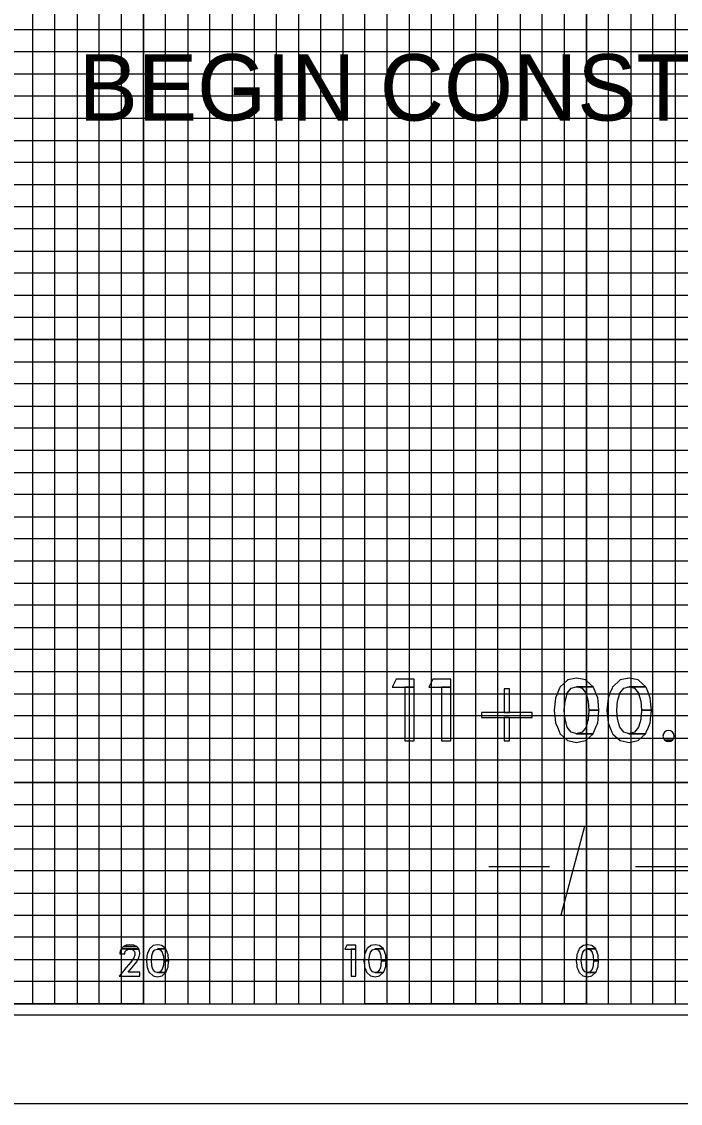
# Model space of a CAD drawing. Extents: x -13 to 323, y -5 to 1431.
# Drawn here: x 134.5 to 164.24, y -4.5 to 44.36 of the extents above; entities that cross this region are included whole.
import ezdxf

# ---------------------------------------------------------------- set-up
doc = ezdxf.new("R2010")
doc.units = 0
for name, color, linetype in [('Prop XS Alignment Label', 7, 'Continuous'), ('Prop XS Offset Labels', 7, 'Continuous'), ('Prop XS Station Labels', 7, 'Continuous'), ('Scratch_Level_3', 7, 'Continuous'), ('Sheet Cross Section CELL', 7, 'Continuous'), ('Sheet Cross Section Grid Major CELL', 7, 'Continuous'), ('Sheet Cross Section Grid Middle CELL', 7, 'Continuous'), ('Sheet Cross Section Grid Minor 1 CELL', 7, 'Continuous'), ('Sheet Cross Section Grid Minor 2 CELL', 7, 'Continuous'), ('Sheet Cutting Line CELL', 7, 'Continuous'), ('Sheet DOT Grid CELL', 7, 'Continuous'), ('Sheet Plot Border Inside CELL', 7, 'Continuous'), ('Sheet Plot Border Outside CELL', 7, 'Continuous')]:
    doc.layers.add(name, color=color, linetype=linetype)

msp = doc.modelspace()

# ---------------------------------------------------------------- linework, layer by layer
at = {"layer": 'Prop XS Alignment Label'}
for p, q in [((155.599, 6.203), (158.324, 6.203)), ((162.211, 6.203), (164.937, 6.203))]:
    msp.add_line(p, q, dxfattribs=at)
msp.add_lwpolyline([(159.913, 8), (158.842, 4), (161.172, 4)], dxfattribs=at)
at = {"layer": 'Prop XS Offset Labels'}
for points in [[(139.051, 1.432), (138.899, 1.25), (139.839, 1.25), (139.839, 1.432), (139.305, 1.432), (139.485, 1.638), (139.681, 1.879), (139.683, 1.881), (139.795, 2.069), (139.794, 2.069), (139.798, 2.074), (139.821, 2.193), (139.833, 2.254), (139.838, 2.279), (139.836, 2.29), (139.835, 2.293), (139.822, 2.354), (139.821, 2.36), (139.819, 2.37), (139.808, 2.421), (139.808, 2.421), (139.805, 2.435), (139.8, 2.461), (139.797, 2.464), (139.794, 2.468), (139.425, 2.468), (139.437, 2.464), (139.445, 2.461), (139.519, 2.435), (139.532, 2.421), (139.583, 2.37), (139.586, 2.36), (139.588, 2.354), (139.609, 2.293), (139.609, 2.29), (139.608, 2.279), (139.608, 2.254), (139.607, 2.193), (139.56, 2.074), (139.558, 2.069), (139.425, 1.881), (139.424, 1.879), (139.223, 1.638)], [(138.935, 2.279), (138.933, 2.254), (139.153, 2.254), (139.155, 2.279), (139.156, 2.29), (139.157, 2.293), (139.179, 2.354), (139.184, 2.36), (139.192, 2.37), (139.232, 2.421), (139.259, 2.435), (139.311, 2.461), (139.317, 2.464), (139.425, 2.468), (139.794, 2.468), (139.784, 2.479), (138.996, 2.479), (138.991, 2.468), (138.989, 2.464), (138.988, 2.461), (138.976, 2.435), (138.97, 2.421), (138.948, 2.37), (138.943, 2.36), (138.942, 2.354), (138.937, 2.293), (138.937, 2.29)], [(139.094, 2.583), (138.996, 2.479), (139.784, 2.479), (139.694, 2.583)], [(139.098, 2.585), (139.094, 2.583), (139.694, 2.583), (139.692, 2.585), (139.56, 2.645), (139.544, 2.652), (139.38, 2.668), (139.38, 2.668), (139.271, 2.652), (139.223, 2.645)], [(140.438, 1.255), (140.637, 1.214), (140.832, 1.255), (140.843, 1.257), (141.008, 1.409), (140.634, 1.409), (140.624, 1.411), (140.619, 1.413), (140.515, 1.442), (140.428, 1.555), (140.427, 1.556), (140.427, 1.556), (140.4, 1.657), (140.399, 1.659), (140.379, 1.732), (140.378, 1.736), (140.36, 1.939), (140.36, 1.941), (140.36, 1.943), (140.378, 2.145), (140.399, 2.222), (140.399, 2.224), (140.426, 2.322), (140.427, 2.325), (140.515, 2.44), (140.627, 2.469), (140.631, 2.47), (140.642, 2.473), (141.012, 2.473), (140.848, 2.622), (140.84, 2.624), (140.639, 2.668), (140.639, 2.668), (140.431, 2.624), (140.429, 2.622), (140.268, 2.473), (140.265, 2.47), (140.264, 2.469), (140.252, 2.44), (140.205, 2.325), (140.203, 2.322), (140.163, 2.224), (140.162, 2.222), (140.155, 2.145), (140.133, 1.943), (140.133, 1.941), (140.133, 1.939), (140.153, 1.736), (140.154, 1.732), (140.161, 1.659), (140.162, 1.657), (140.203, 1.556), (140.203, 1.555), (140.249, 1.442), (140.261, 1.413), (140.262, 1.411), (140.265, 1.409), (140.435, 1.257)], [(140.898, 2.145), (140.915, 1.943), (141.142, 1.943), (141.122, 2.145), (141.115, 2.222), (141.114, 2.224), (141.114, 2.224), (141.074, 2.322), (141.074, 2.322), (141.073, 2.325), (141.027, 2.44), (141.027, 2.44), (141.015, 2.469), (141.015, 2.47), (141.012, 2.473), (140.642, 2.473), (140.651, 2.47), (140.655, 2.469), (140.761, 2.44), (140.849, 2.325), (140.851, 2.322), (140.877, 2.224), (140.878, 2.222)], [(149.174, 2.641), (149.085, 2.459), (149.583, 2.459), (149.583, 2.641)], [(149.374, 2.459), (149.374, 1.25), (149.583, 1.25), (149.583, 2.459)], [(150.258, 1.255), (150.458, 1.214), (150.652, 1.255), (150.663, 1.257), (150.828, 1.409), (150.454, 1.409), (150.445, 1.411), (150.44, 1.413), (150.335, 1.442), (150.248, 1.555), (150.248, 1.556), (150.248, 1.556), (150.22, 1.657), (150.22, 1.659), (150.2, 1.732), (150.198, 1.736), (150.181, 1.939), (150.181, 1.941), (150.181, 1.943), (150.198, 2.145), (150.219, 2.222), (150.22, 2.224), (150.246, 2.322), (150.247, 2.325), (150.335, 2.44), (150.448, 2.469), (150.452, 2.47), (150.462, 2.473), (150.832, 2.473), (150.669, 2.622), (150.66, 2.624), (150.46, 2.668), (150.46, 2.668), (150.252, 2.624), (150.25, 2.622), (150.088, 2.473), (150.085, 2.47), (150.084, 2.469), (150.072, 2.44), (150.025, 2.325), (150.024, 2.322), (149.983, 2.224), (149.983, 2.222), (149.975, 2.145), (149.954, 1.943), (149.953, 1.941), (149.954, 1.939), (149.974, 1.736), (149.974, 1.732), (149.982, 1.659), (149.982, 1.657), (150.023, 1.556), (150.024, 1.555), (150.07, 1.442), (150.082, 1.413), (150.083, 1.411), (150.085, 1.409), (150.255, 1.257)], [(150.719, 2.145), (150.735, 1.943), (150.962, 1.943), (150.942, 2.145), (150.935, 2.222), (150.934, 2.224), (150.934, 2.224), (150.895, 2.322), (150.895, 2.322), (150.893, 2.325), (150.847, 2.44), (150.847, 2.44), (150.835, 2.469), (150.835, 2.47), (150.832, 2.473), (150.462, 2.473), (150.472, 2.47), (150.475, 2.469), (150.582, 2.44), (150.669, 2.325), (150.672, 2.322), (150.698, 2.224), (150.698, 2.222)], [(159.844, 1.255), (160.044, 1.214), (160.238, 1.255), (160.249, 1.257), (160.415, 1.409), (160.041, 1.409), (160.031, 1.411), (160.026, 1.413), (159.922, 1.442), (159.834, 1.555), (159.834, 1.556), (159.834, 1.556), (159.806, 1.657), (159.806, 1.659), (159.786, 1.732), (159.785, 1.736), (159.767, 1.939), (159.767, 1.941), (159.767, 1.943), (159.785, 2.145), (159.805, 2.222), (159.806, 2.224), (159.833, 2.322), (159.833, 2.325), (159.922, 2.44), (160.034, 2.469), (160.038, 2.47), (160.048, 2.473), (160.418, 2.473), (160.255, 2.622), (160.247, 2.624), (160.046, 2.668), (160.046, 2.668), (159.838, 2.624), (159.836, 2.622), (159.675, 2.473), (159.672, 2.47), (159.671, 2.469), (159.658, 2.44), (159.611, 2.325), (159.61, 2.322), (159.57, 2.224), (159.569, 2.222), (159.561, 2.145), (159.54, 1.943), (159.54, 1.941), (159.54, 1.939), (159.56, 1.736), (159.561, 1.732), (159.568, 1.659), (159.568, 1.657), (159.61, 1.556), (159.61, 1.555), (159.656, 1.442), (159.668, 1.413), (159.669, 1.411), (159.672, 1.409), (159.842, 1.257)], [(159.844, 1.255), (160.044, 1.214), (160.238, 1.255), (160.249, 1.257), (160.415, 1.409), (160.041, 1.409), (160.031, 1.411), (160.026, 1.413), (159.922, 1.442), (159.834, 1.555), (159.834, 1.556), (159.834, 1.556), (159.806, 1.657), (159.806, 1.659), (159.786, 1.732), (159.785, 1.736), (159.767, 1.939), (159.767, 1.941), (159.767, 1.943), (159.785, 2.145), (159.805, 2.222), (159.806, 2.224), (159.833, 2.322), (159.833, 2.325), (159.922, 2.44), (160.034, 2.469), (160.038, 2.47), (160.048, 2.473), (160.418, 2.473), (160.255, 2.622), (160.247, 2.624), (160.046, 2.668), (160.046, 2.668), (159.838, 2.624), (159.836, 2.622), (159.675, 2.473), (159.672, 2.47), (159.671, 2.469), (159.658, 2.44), (159.611, 2.325), (159.61, 2.322), (159.57, 2.224), (159.569, 2.222), (159.561, 2.145), (159.54, 1.943), (159.54, 1.941), (159.54, 1.939), (159.56, 1.736), (159.561, 1.732), (159.568, 1.659), (159.568, 1.657), (159.61, 1.556), (159.61, 1.555), (159.656, 1.442), (159.668, 1.413), (159.669, 1.411), (159.672, 1.409), (159.842, 1.257)], [(160.305, 2.145), (160.322, 1.943), (160.549, 1.943), (160.529, 2.145), (160.522, 2.222), (160.521, 2.224), (160.52, 2.224), (160.481, 2.322), (160.481, 2.322), (160.48, 2.325), (160.434, 2.44), (160.434, 2.44), (160.422, 2.469), (160.422, 2.47), (160.418, 2.473), (160.048, 2.473), (160.058, 2.47), (160.061, 2.469), (160.168, 2.44), (160.255, 2.325), (160.258, 2.322), (160.284, 2.224), (160.285, 2.222)], [(160.305, 2.145), (160.322, 1.943), (160.549, 1.943), (160.529, 2.145), (160.522, 2.222), (160.521, 2.224), (160.52, 2.224), (160.481, 2.322), (160.481, 2.322), (160.48, 2.325), (160.434, 2.44), (160.434, 2.44), (160.422, 2.469), (160.422, 2.47), (160.418, 2.473), (160.048, 2.473), (160.058, 2.47), (160.061, 2.469), (160.168, 2.44), (160.255, 2.325), (160.258, 2.322), (160.284, 2.224), (160.285, 2.222)], [(140.644, 1.411), (140.634, 1.409), (141.008, 1.409), (141.011, 1.411), (141.013, 1.413), (141.025, 1.442), (141.071, 1.555), (141.072, 1.556), (141.113, 1.657), (141.114, 1.659), (141.121, 1.732), (141.122, 1.736), (141.142, 1.939), (141.142, 1.941), (141.142, 1.943), (140.915, 1.943), (140.915, 1.941), (140.914, 1.939), (140.898, 1.736), (140.898, 1.732), (140.878, 1.659), (140.878, 1.657), (140.851, 1.556), (140.85, 1.555), (140.761, 1.442), (140.649, 1.413)], [(150.465, 1.411), (150.454, 1.409), (150.828, 1.409), (150.831, 1.411), (150.833, 1.413), (150.845, 1.442), (150.892, 1.555), (150.892, 1.556), (150.934, 1.657), (150.935, 1.659), (150.942, 1.732), (150.942, 1.736), (150.962, 1.939), (150.963, 1.941), (150.962, 1.943), (150.735, 1.943), (150.735, 1.941), (150.735, 1.939), (150.719, 1.736), (150.718, 1.732), (150.699, 1.659), (150.698, 1.657), (150.671, 1.556), (150.67, 1.555), (150.582, 1.442), (150.47, 1.413)], [(160.051, 1.411), (160.041, 1.409), (160.415, 1.409), (160.418, 1.411), (160.419, 1.413), (160.431, 1.442), (160.478, 1.555), (160.479, 1.556), (160.52, 1.657), (160.521, 1.659), (160.528, 1.732), (160.529, 1.736), (160.549, 1.939), (160.549, 1.941), (160.549, 1.943), (160.321, 1.943), (160.321, 1.941), (160.321, 1.939), (160.305, 1.736), (160.305, 1.732), (160.285, 1.659), (160.285, 1.657), (160.257, 1.556), (160.257, 1.555), (160.168, 1.442), (160.056, 1.413)], [(160.051, 1.411), (160.041, 1.409), (160.415, 1.409), (160.418, 1.411), (160.419, 1.413), (160.431, 1.442), (160.478, 1.555), (160.479, 1.556), (160.52, 1.657), (160.521, 1.659), (160.528, 1.732), (160.529, 1.736), (160.549, 1.939), (160.549, 1.941), (160.549, 1.943), (160.321, 1.943), (160.321, 1.941), (160.321, 1.939), (160.305, 1.736), (160.305, 1.732), (160.285, 1.659), (160.285, 1.657), (160.257, 1.556), (160.257, 1.555), (160.168, 1.442), (160.056, 1.413)]]:
    msp.add_lwpolyline(points, close=True, dxfattribs=at)
at = {"layer": 'Prop XS Station Labels'}
for points in [[(159.155, 11.885), (159.554, 11.803), (159.943, 11.885), (159.965, 11.89), (160.295, 12.193), (159.547, 12.193), (159.528, 12.199), (159.518, 12.201), (159.309, 12.26), (159.135, 12.487), (159.134, 12.489), (159.134, 12.489), (159.079, 12.69), (159.078, 12.694), (159.038, 12.84), (159.035, 12.849), (159, 13.253), (159, 13.258), (159, 13.262), (159.035, 13.666), (159.077, 13.82), (159.078, 13.824), (159.131, 14.02), (159.133, 14.027), (159.309, 14.255), (159.535, 14.314), (159.542, 14.316), (159.563, 14.321), (160.303, 14.321), (159.976, 14.62), (159.96, 14.624), (159.558, 14.712), (159.558, 14.712), (159.142, 14.624), (159.138, 14.62), (158.815, 14.321), (158.809, 14.316), (158.807, 14.314), (158.783, 14.255), (158.689, 14.027), (158.686, 14.02), (158.605, 13.824), (158.605, 13.82), (158.589, 13.666), (158.546, 13.262), (158.545, 13.258), (158.546, 13.253), (158.586, 12.849), (158.587, 12.84), (158.602, 12.694), (158.603, 12.69), (158.685, 12.489), (158.686, 12.487), (158.778, 12.26), (158.802, 12.201), (158.804, 12.199), (158.81, 12.193), (159.149, 11.89)], [(161.527, 11.885), (161.926, 11.803), (162.315, 11.885), (162.337, 11.89), (162.668, 12.193), (161.92, 12.193), (161.9, 12.199), (161.891, 12.201), (161.682, 12.26), (161.507, 12.487), (161.507, 12.489), (161.506, 12.489), (161.451, 12.69), (161.45, 12.694), (161.41, 12.84), (161.408, 12.849), (161.373, 13.253), (161.373, 13.258), (161.373, 13.262), (161.408, 13.666), (161.45, 13.82), (161.45, 13.824), (161.504, 14.02), (161.505, 14.027), (161.682, 14.255), (161.907, 14.314), (161.915, 14.316), (161.935, 14.321), (162.675, 14.321), (162.349, 14.62), (162.332, 14.624), (161.931, 14.712), (161.93, 14.712), (161.515, 14.624), (161.51, 14.62), (161.188, 14.321), (161.182, 14.316), (161.18, 14.314), (161.155, 14.255), (161.061, 14.027), (161.059, 14.02), (160.978, 13.824), (160.977, 13.82), (160.961, 13.666), (160.919, 13.262), (160.918, 13.258), (160.919, 13.253), (160.959, 12.849), (160.96, 12.84), (160.975, 12.694), (160.975, 12.69), (161.058, 12.489), (161.059, 12.487), (161.151, 12.26), (161.175, 12.201), (161.176, 12.199), (161.182, 12.193), (161.522, 11.89)], [(151.405, 14.658), (151.226, 14.293), (152.224, 14.293), (152.224, 14.658)], [(151.805, 14.293), (151.805, 11.876), (152.224, 11.876), (152.224, 14.293)], [(153.059, 14.658), (152.881, 14.293), (153.878, 14.293), (153.878, 14.658)], [(153.46, 14.293), (153.46, 11.876), (153.878, 11.876), (153.878, 14.293)], [(156.291, 14.218), (156.291, 13.16), (156.518, 13.16), (156.518, 14.218)], [(160.076, 13.666), (160.109, 13.262), (160.563, 13.262), (160.524, 13.666), (160.509, 13.82), (160.507, 13.824), (160.507, 13.824), (160.428, 14.02), (160.428, 14.02), (160.425, 14.027), (160.334, 14.255), (160.333, 14.255), (160.31, 14.314), (160.309, 14.316), (160.303, 14.321), (159.563, 14.321), (159.582, 14.316), (159.589, 14.314), (159.802, 14.255), (159.977, 14.027), (159.982, 14.02), (160.034, 13.824), (160.035, 13.82)], [(162.449, 13.666), (162.482, 13.262), (162.936, 13.262), (162.896, 13.666), (162.882, 13.82), (162.88, 13.824), (162.88, 13.824), (162.801, 14.02), (162.8, 14.02), (162.798, 14.027), (162.706, 14.255), (162.706, 14.255), (162.682, 14.314), (162.682, 14.316), (162.675, 14.321), (161.935, 14.321), (161.955, 14.316), (161.961, 14.314), (162.175, 14.255), (162.35, 14.027), (162.355, 14.02), (162.407, 13.824), (162.408, 13.82)], [(159.568, 12.199), (159.547, 12.193), (160.295, 12.193), (160.301, 12.199), (160.305, 12.201), (160.329, 12.26), (160.422, 12.487), (160.423, 12.489), (160.506, 12.69), (160.508, 12.694), (160.522, 12.84), (160.523, 12.849), (160.563, 13.253), (160.564, 13.258), (160.563, 13.262), (160.109, 13.262), (160.109, 13.258), (160.108, 13.253), (160.076, 12.849), (160.075, 12.84), (160.036, 12.694), (160.035, 12.69), (159.981, 12.489), (159.979, 12.487), (159.802, 12.26), (159.578, 12.201)], [(161.94, 12.199), (161.92, 12.193), (162.668, 12.193), (162.674, 12.199), (162.677, 12.201), (162.701, 12.26), (162.795, 12.487), (162.796, 12.489), (162.879, 12.69), (162.881, 12.694), (162.895, 12.84), (162.896, 12.849), (162.936, 13.253), (162.936, 13.258), (162.936, 13.262), (162.481, 13.262), (162.481, 13.258), (162.481, 13.253), (162.449, 12.849), (162.448, 12.84), (162.409, 12.694), (162.408, 12.69), (162.354, 12.489), (162.352, 12.487), (162.175, 12.26), (161.951, 12.201)], [(155.255, 13.16), (155.255, 12.933), (157.554, 12.933), (157.554, 13.16)], [(156.291, 12.933), (156.291, 11.876), (156.518, 11.876), (156.518, 12.933)], [(163.475, 11.994), (163.529, 11.913), (163.885, 11.913), (163.938, 11.994), (163.957, 12.09), (163.938, 12.186), (163.885, 12.267), (163.803, 12.32), (163.706, 12.34), (163.61, 12.32), (163.529, 12.267), (163.475, 12.186), (163.455, 12.09)], [(163.61, 11.858), (163.706, 11.84), (163.803, 11.858), (163.885, 11.913), (163.529, 11.913)]]:
    msp.add_lwpolyline(points, close=True, dxfattribs=at)
at = {"layer": 'Scratch_Level_3'}
msp.add_lwpolyline([(20, 40), (300, 40), (300, 10), (20, 10)], close=True, dxfattribs=at)
at = {"layer": 'Sheet Cross Section CELL'}
msp.add_lwpolyline([(320, 210), (0, 210), (0, 0), (320, 0)], close=True, dxfattribs=at)
at = {"layer": 'Sheet Cross Section Grid Major CELL'}
for p, q in [((140, 210), (140, 0)), ((150, 0), (150, 210)), ((160, 210), (160, 0)), ((140, 0), (130, 0)), ((160, 0), (150, 0))]:
    msp.add_line(p, q, dxfattribs=at)
for points in [[(0, 40), (320, 40), (320, 30), (0, 30)], [(0, 20), (320, 20), (320, 10), (0, 10)]]:
    msp.add_lwpolyline(points, dxfattribs=at)
at = {"layer": 'Sheet Cross Section Grid Middle CELL'}
for points in [[(125, 0), (135, 0), (135, 210)], [(145, 210), (145, 0), (155, 0), (155, 210)], [(0, 25), (320, 25), (320, 35), (0, 35)], [(0, 5), (320, 5), (320, 15), (0, 15)]]:
    msp.add_lwpolyline(points, dxfattribs=at)
at = {"layer": 'Sheet Cross Section Grid Minor 1 CELL'}
for points in [[(0, 44), (320, 44), (320, 43), (0, 43)], [(0, 42), (320, 42), (320, 41), (0, 41)], [(0, 39), (320, 39), (320, 38), (0, 38)], [(0, 37), (320, 37), (320, 36), (0, 36)], [(0, 34), (320, 34), (320, 33), (0, 33)], [(0, 32), (320, 32), (320, 31), (0, 31)], [(0, 29), (320, 29), (320, 28), (0, 28)], [(0, 27), (320, 27), (320, 26), (0, 26)], [(0, 24), (320, 24), (320, 23), (0, 23)], [(0, 22), (320, 22), (320, 21), (0, 21)], [(0, 19), (320, 19), (320, 18), (0, 18)], [(0, 17), (320, 17), (320, 16), (0, 16)], [(0, 14), (320, 14), (320, 13), (0, 13)], [(0, 12), (320, 12), (320, 11), (0, 11)], [(0, 9), (320, 9), (320, 8), (0, 8)], [(0, 7), (320, 7), (320, 6), (0, 6)], [(0, 4), (320, 4), (320, 3), (0, 3)], [(0, 2), (320, 2), (320, 1), (0, 1)]]:
    msp.add_lwpolyline(points, dxfattribs=at)
at = {"layer": 'Sheet Cross Section Grid Minor 2 CELL'}
for points in [[(135, 0), (136, 0), (136, 210), (137, 210), (137, 0)], [(137, 0), (138, 0), (138, 210), (139, 210), (139, 0)], [(140, 0), (141, 0), (141, 210), (142, 210), (142, 0)], [(142, 0), (143, 0), (143, 210), (144, 210), (144, 0)], [(145, 0), (146, 0), (146, 210), (147, 210), (147, 0)], [(147, 0), (148, 0), (148, 210), (149, 210), (149, 0)], [(150, 0), (151, 0), (151, 210), (152, 210), (152, 0)], [(152, 0), (153, 0), (153, 210), (154, 210), (154, 0)], [(155, 0), (156, 0), (156, 210), (157, 210), (157, 0)], [(157, 0), (158, 0), (158, 210), (159, 210), (159, 0)], [(160, 0), (161, 0), (161, 210), (162, 210), (162, 0)], [(162, 0), (163, 0), (163, 210), (164, 210), (164, 0)]]:
    msp.add_lwpolyline(points, dxfattribs=at)
at = {"layer": 'Sheet Cutting Line CELL'}
msp.add_line((-13.4, -4.5), (323.3, -4.5), dxfattribs=at)
at = {"layer": 'Sheet DOT Grid CELL'}
for p, q in [((140, 0), (140, 210)), ((150, 0), (150, 210)), ((160, 0), (160, 210)), ((0, 40), (320, 40)), ((0, 30), (320, 30)), ((0, 20), (320, 20)), ((0, 10), (320, 10))]:
    msp.add_line(p, q, dxfattribs=at)
at = {"layer": 'Sheet Plot Border Inside CELL'}
msp.add_lwpolyline([(-10.8, -0.5), (322.4, -0.5), (322.4, 210.5), (-10.8, 210.5)], close=True, dxfattribs=at)
at = {"layer": 'Sheet Plot Border Outside CELL'}
msp.add_lwpolyline([(-13.4, -4.5), (323.3, -4.5), (323.3, 214.5), (-13.4, 214.5)], close=True, dxfattribs=at)

# ---------------------------------------------------------------- texts
at = {"layer": 'Prop XS Station Labels'}
msp.add_text('BEGIN CONSTRUCTION', height=3, dxfattribs=at).set_placement((137.07, 39.893))

doc.saveas('drawing.dxf')
